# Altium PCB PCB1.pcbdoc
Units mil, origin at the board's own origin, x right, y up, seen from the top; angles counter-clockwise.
Board outline 2786 x 2316 mil, 2 copper layers (Top Layer, Bottom Layer), stack 62.2 mil thick; 3 components, 3 nets, 9 pads, 115 vias.
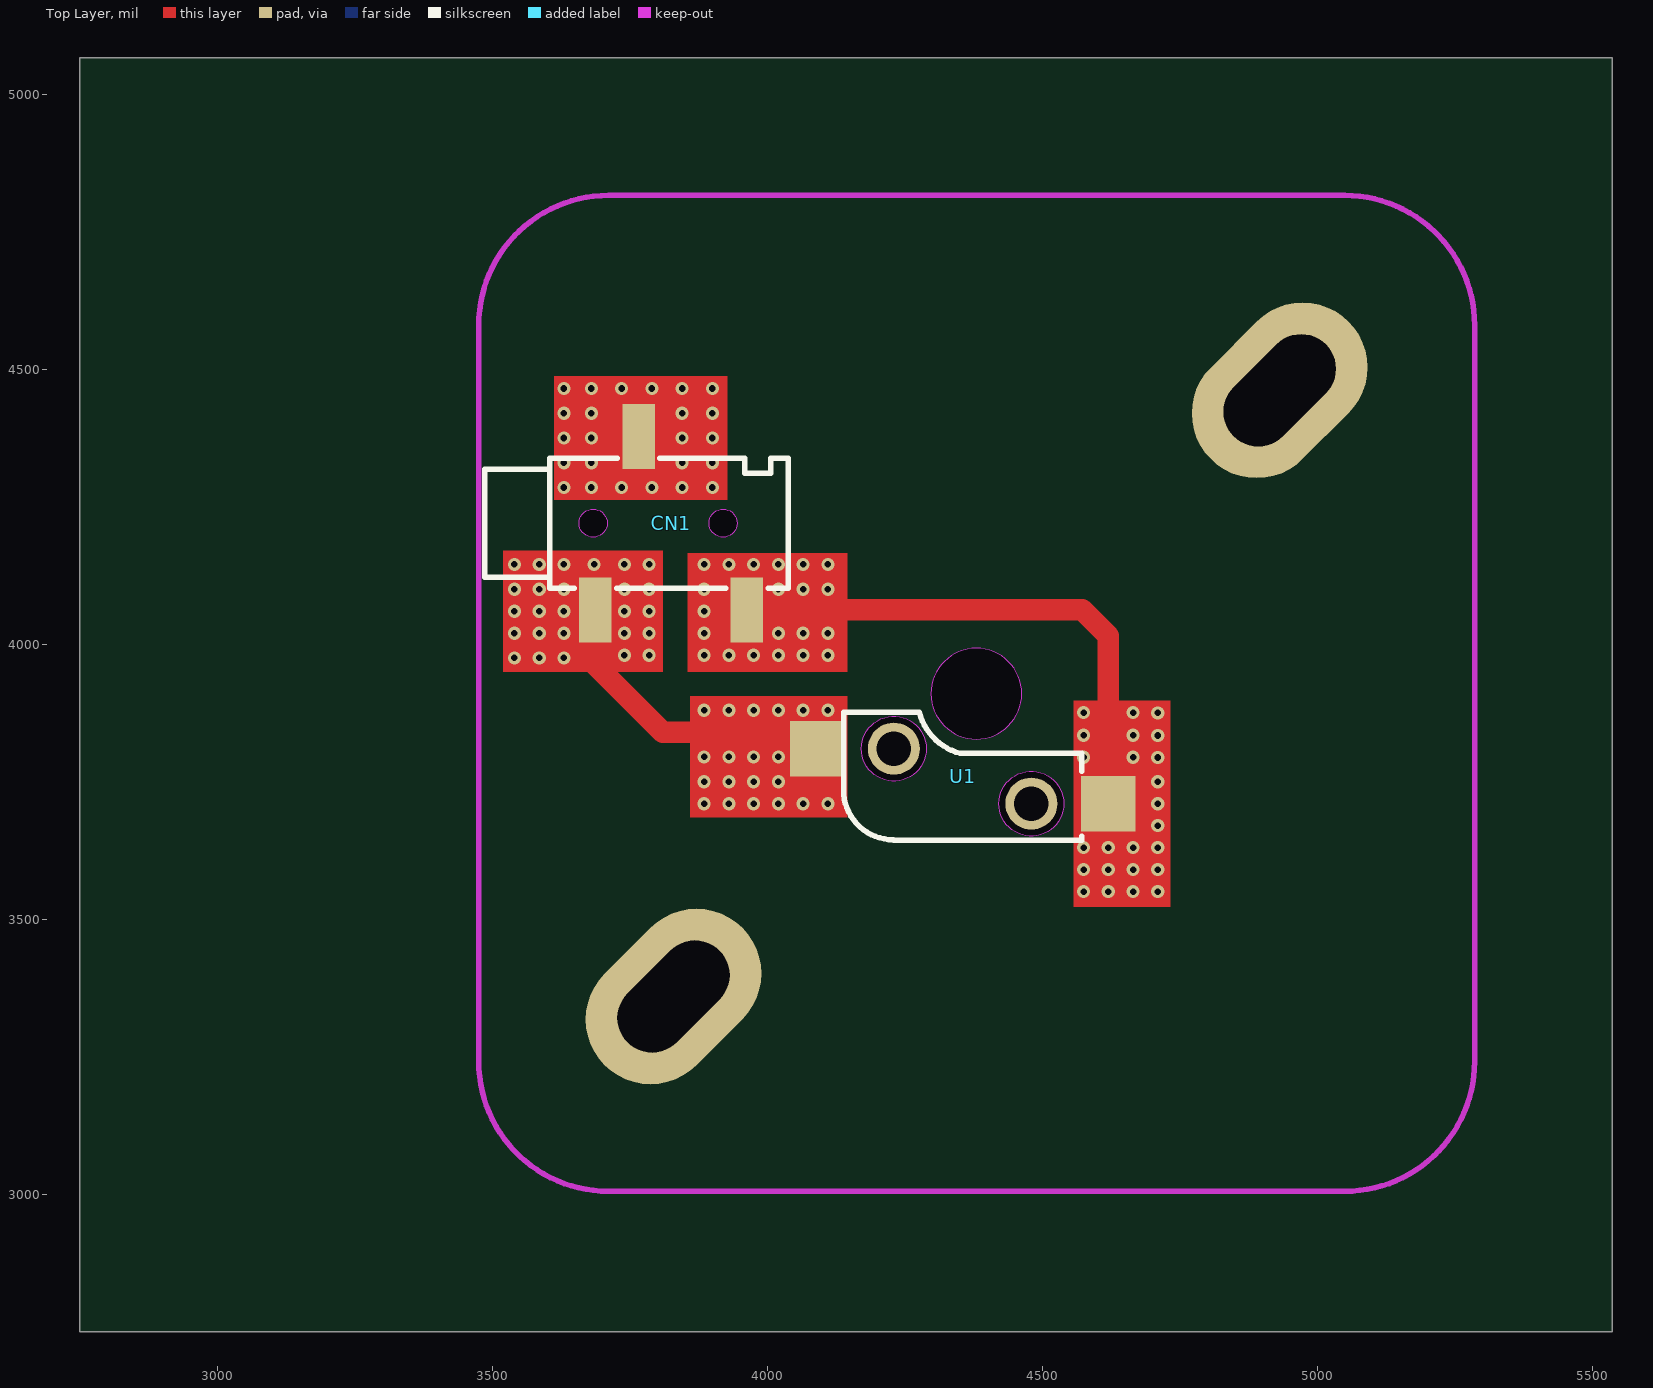
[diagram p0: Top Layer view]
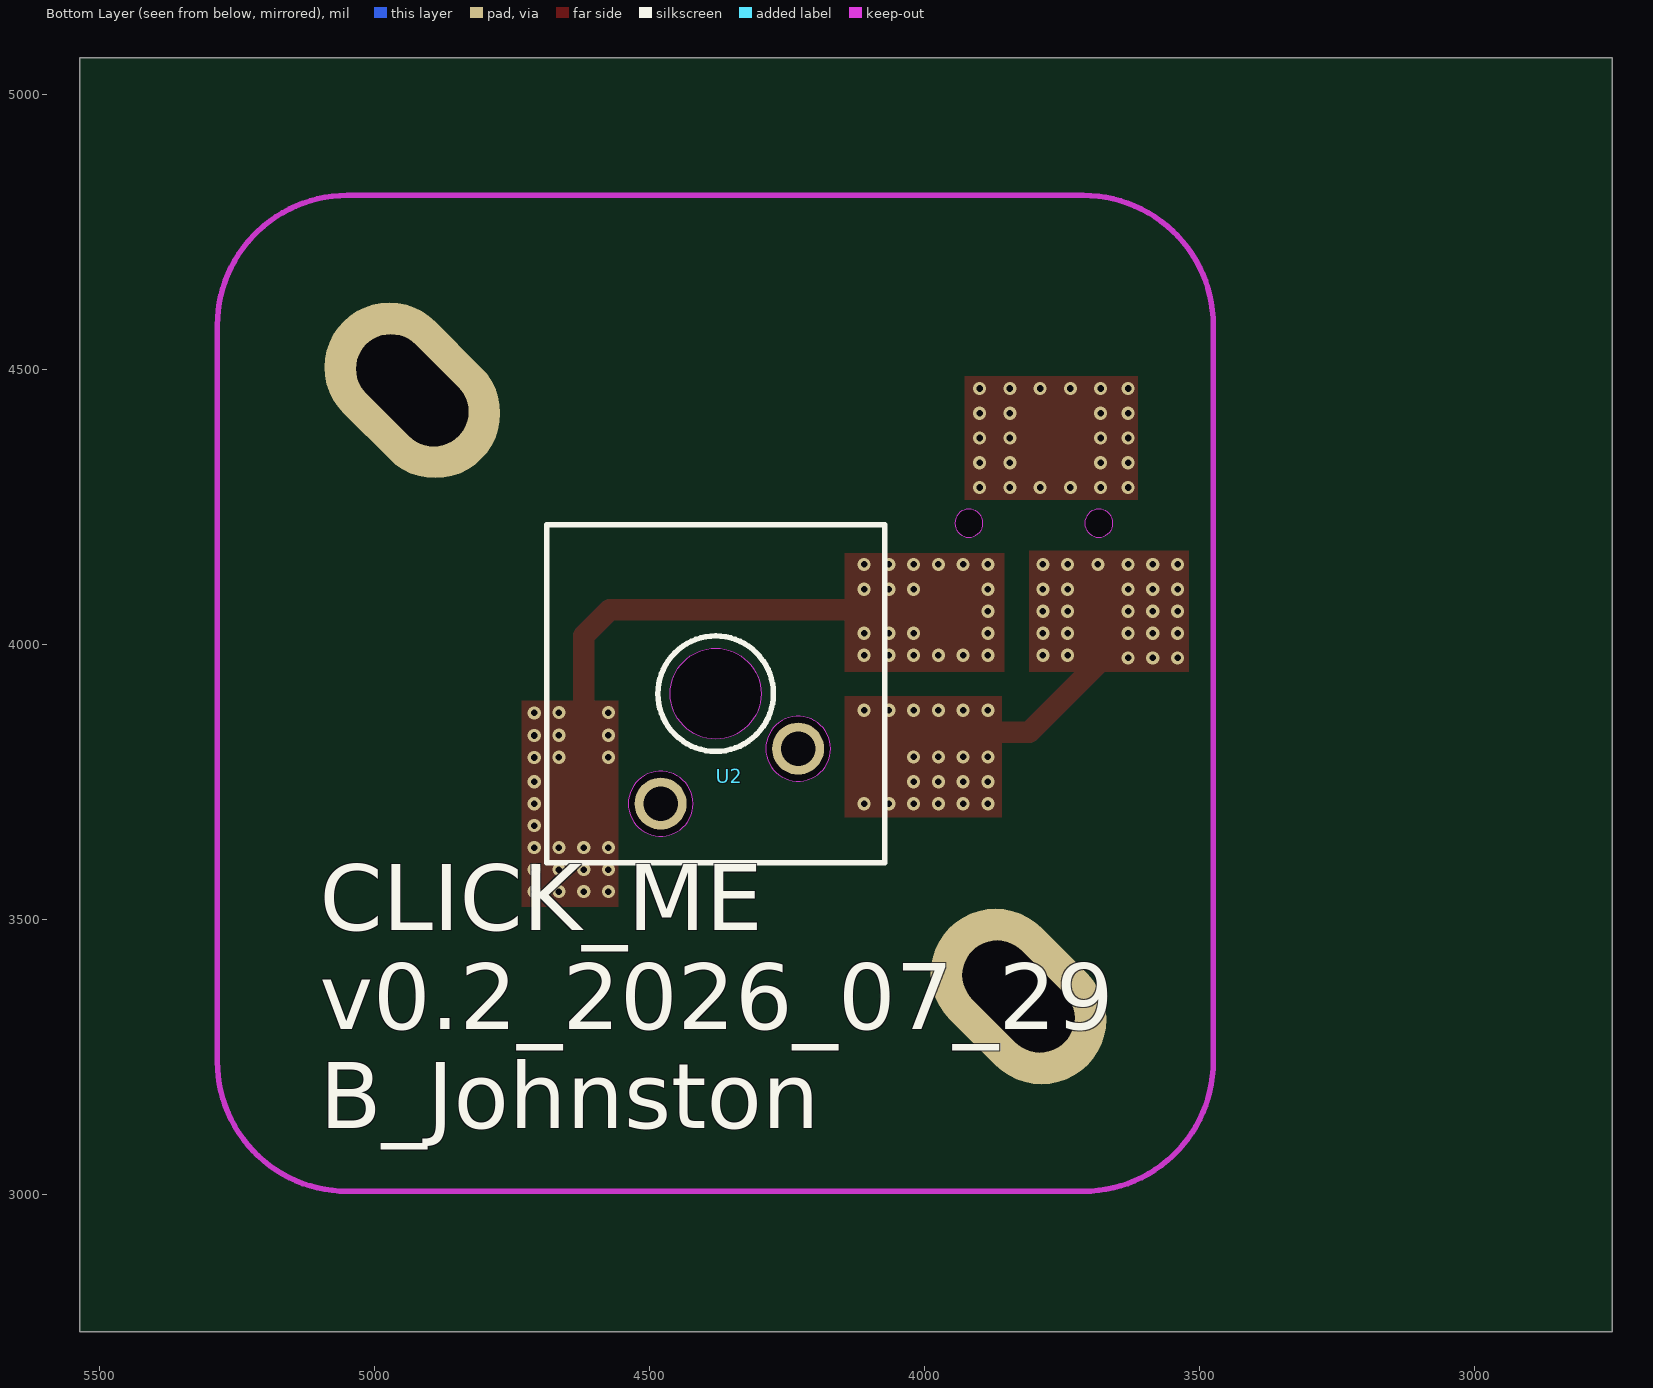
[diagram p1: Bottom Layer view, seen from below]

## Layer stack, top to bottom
Top Solder Mask Layer: solder mask 0.4, Dk 3.3
Top Layer: signal copper 1.4
Dielectric1: surface 59.4, FR4, Dk 4.5
Bottom Layer: signal copper 1.4
Bottom Solder Mask Layer: solder mask 0.4, Dk 3.3

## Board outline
5536,2750 2750,2750 2750,5066 5536,5066

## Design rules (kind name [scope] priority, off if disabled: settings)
BoardOutlineClearance copperThickness1oz [All] p0: genericclearance=10 ignorepadtopadclearanceinfootprint=FALSE except(0: Arc-SplitContinuation Track-SplitContinuation SMDPad-SplitContinuation THPad-SplitContinuation Via-SplitContinuation Fill-SplitContinuation Poly-SplitContinuation Region-SplitContinuation Text-SplitContinuation)
BoardOutlineClearance copperThickness2oz [All] p0: genericclearance=10 ignorepadtopadclearanceinfootprint=FALSE except(0: Arc-SplitContinuation Track-SplitContinuation SMDPad-SplitContinuation THPad-SplitContinuation Via-SplitContinuation Fill-SplitContinuation Poly-SplitContinuation Region-SplitContinuation Text-SplitContinuation)
BoardOutlineClearance otherClearance [All] p0: genericclearance=10 ignorepadtopadclearanceinfootprint=FALSE except(0: Arc-SplitContinuation Track-SplitContinuation SMDPad-SplitContinuation THPad-SplitContinuation Via-SplitContinuation Fill-SplitContinuation Poly-SplitContinuation Region-SplitContinuation Text-SplitContinuation)
Clearance copperThickness1oz [All] p1: gap=7 ignorepadtopadclearanceinfootprint=FALSE
Clearance copperThickness2oz [All] p1: gap=7 ignorepadtopadclearanceinfootprint=FALSE
Clearance otherClearance [All] p1: gap=7 ignorepadtopadclearanceinfootprint=FALSE
DiffPairsRouting differentialPair [All] p1: maxuncoupledlength=10 minlimit=6 maxlimit=Infinity mostfreqgap=6 toplayer_minwidth=5 toplayer_prefwidth=10 toplayer_maxwidth=100 bottomlayer_minwidth=5 bottomlayer_prefwidth=10 bottomlayer_maxwidth=100
PasteMaskExpansion pasteMaskExpansion [All] p1: expansion=0
PlaneConnect innerPlane [All] p1: planeconnectstyle=Relief reliefexpansion=20 reliefentries=4 reliefconductorwidth=10 reliefairgap=10
PolygonConnect copperRegion [All] p1: connectstyle=Relief reliefentries=4 reliefconductorwidth=10 polygonreliefangle="90 Angle" airgapwidth=10
RoutingVias viaSize [All] p1: viastyle="Through Hole" holewidth=12.0078 minholewidth=11.811 maxholewidth=248.0314 width=12.0078 minwidth=11.811 maxwidth=248.0314
SolderMaskExpansion solderMaskExpansion [IsVia] p1: useseparateexpansions=TRUE expansion=-1000 expansionbottom=-1000
SolderMaskExpansion solderMaskExpansion [All] p2: useseparateexpansions=TRUE expansion=2 expansionbottom=2
Width copperThickness1oz [All] p1: maxlimit=100 minlimit=5 preferedwidth=10
Width copperThickness2oz [All] p1: maxlimit=100 minlimit=8 preferedwidth=10

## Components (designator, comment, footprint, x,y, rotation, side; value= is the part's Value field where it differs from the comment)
CN1 "PJ-320B" AUDIO-SMD_PJ-320B 3825,4220 r90 top
U1 "CPG151101S11-16" SMD_KEYBOARD-SW 4355,3760 r0 top
U2 "CPG151101D13" KEY-TH_CPG151101D21X 4355,3760 r0 bottom

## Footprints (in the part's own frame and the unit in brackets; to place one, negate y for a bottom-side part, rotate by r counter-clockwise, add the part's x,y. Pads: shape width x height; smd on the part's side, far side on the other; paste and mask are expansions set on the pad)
AUDIO-SMD_PJ-320B [mil]
  rect 118.1x59.1 smd: 1(-157.5,137.8) 2(157.5,59.1) 3(-157.5,-137.8)
  Board Outline Layer lines w0.1: 0,167.3 -4.4,166.9 -8.8,165.8 -12.8,163.9 -16.4,161.3 -19.6,158.2 -22.2,154.5 -24,150.5 -25.2,146.2 -25.6,141.7 -25.2,137.3 -24,133 -22.2,128.9 -19.6,125.3 -16.4,122.1 -12.8,119.6 -8.8,117.7 -4.4,116.5 0,116.1 4.4,116.5 8.8,117.7 12.8,119.6 16.4,122.1 19.6,125.3 22.2,128.9 24,133 25.2,137.3 25.6,141.7 25.2,146.2 24,150.5 22.2,154.5 19.6,158.2 16.4,161.3 12.8,163.9 8.8,165.8 4.4,166.9 0,167.3 ; 0,-68.9 -4.4,-69.3 -8.8,-70.4 -12.8,-72.3 -16.4,-74.9 -19.6,-78 -22.2,-81.7 -24,-85.7 -25.2,-90 -25.6,-94.5 -25.2,-98.9 -24,-103.2 -22.2,-107.3 -19.6,-110.9 -16.4,-114.1 -12.8,-116.6 -8.8,-118.5 -4.4,-119.7 0,-120.1 4.4,-119.7 8.8,-118.5 12.8,-116.6 16.4,-114.1 19.6,-110.9 22.2,-107.3 24,-103.2 25.2,-98.9 25.6,-94.5 25.2,-90 24,-85.7 22.2,-81.7 19.6,-78 16.4,-74.9 12.8,-72.3 8.8,-70.4 4.4,-69.3 0,-68.9
  Board Outline Layer region: 25.6,141.7 25.2,137.3 24,133 22.2,128.9 19.6,125.3 16.4,122.1 12.8,119.6 8.8,117.7 4.4,116.5 0,116.1 -4.4,116.5 -8.8,117.7 -12.8,119.6 -16.4,122.1 -19.6,125.3 -22.2,128.9 -24,133 -25.2,137.3 -25.6,141.7 -25.2,146.2 -24,150.5 -22.2,154.5 -19.6,158.2 -16.4,161.3 -12.8,163.9 -8.8,165.8 -4.4,166.9 0,167.3 4.4,166.9 8.8,165.8 12.8,163.9 16.4,161.3 19.6,158.2 22.2,154.5 24,150.5 25.2,146.2
  Board Outline Layer region: 25.6,141.7 25.2,137.3 24,133 22.2,128.9 19.6,125.3 16.4,122.1 12.8,119.6 8.8,117.7 4.4,116.5 0,116.1 -4.4,116.5 -8.8,117.7 -12.8,119.6 -16.4,122.1 -19.6,125.3 -22.2,128.9 -24,133 -25.2,137.3 -25.6,141.7 -25.2,146.2 -24,150.5 -22.2,154.5 -19.6,158.2 -16.4,161.3 -12.8,163.9 -8.8,165.8 -4.4,166.9 0,167.3 4.4,166.9 8.8,165.8 12.8,163.9 16.4,161.3 19.6,158.2 22.2,154.5 24,150.5 25.2,146.2
  Board Outline Layer region: 25.6,-94.5 25.2,-98.9 24,-103.2 22.2,-107.3 19.6,-110.9 16.4,-114.1 12.8,-116.6 8.8,-118.5 4.4,-119.7 0,-120.1 -4.4,-119.7 -8.8,-118.5 -12.8,-116.6 -16.4,-114.1 -19.6,-110.9 -22.2,-107.3 -24,-103.2 -25.2,-98.9 -25.6,-94.5 -25.2,-90 -24,-85.7 -22.2,-81.7 -19.6,-78 -16.4,-74.9 -12.8,-72.3 -8.8,-70.4 -4.4,-69.3 0,-68.9 4.4,-69.3 8.8,-70.4 12.8,-72.3 16.4,-74.9 19.6,-78 22.2,-81.7 24,-85.7 25.2,-90
  Board Outline Layer region: 25.6,-94.5 25.2,-98.9 24,-103.2 22.2,-107.3 19.6,-110.9 16.4,-114.1 12.8,-116.6 8.8,-118.5 4.4,-119.7 0,-120.1 -4.4,-119.7 -8.8,-118.5 -12.8,-116.6 -16.4,-114.1 -19.6,-110.9 -22.2,-107.3 -24,-103.2 -25.2,-98.9 -25.6,-94.5 -25.2,-90 -24,-85.7 -22.2,-81.7 -19.6,-78 -16.4,-74.9 -12.8,-72.3 -8.8,-70.4 -4.4,-69.3 0,-68.9 4.4,-69.3 8.8,-70.4 12.8,-72.3 16.4,-74.9 19.6,-78 22.2,-81.7 24,-85.7 25.2,-90
  Multi-Layer board cut-out: 25.6,141.7 25.2,137.3 24,133 22.2,128.9 19.6,125.3 16.4,122.1 12.8,119.6 8.8,117.7 4.4,116.5 0,116.1 -4.4,116.5 -8.8,117.7 -12.8,119.6 -16.4,122.1 -19.6,125.3 -22.2,128.9 -24,133 -25.2,137.3 -25.6,141.7 -25.2,146.2 -24,150.5 -22.2,154.5 -19.6,158.2 -16.4,161.3 -12.8,163.9 -8.8,165.8 -4.4,166.9 0,167.3 4.4,166.9 8.8,165.8 12.8,163.9 16.4,161.3 19.6,158.2 22.2,154.5 24,150.5 25.2,146.2
  Multi-Layer board cut-out: 25.6,-94.5 25.2,-98.9 24,-103.2 22.2,-107.3 19.6,-110.9 16.4,-114.1 12.8,-116.6 8.8,-118.5 4.4,-119.7 0,-120.1 -4.4,-119.7 -8.8,-118.5 -12.8,-116.6 -16.4,-114.1 -19.6,-110.9 -22.2,-107.3 -24,-103.2 -25.2,-98.9 -25.6,-94.5 -25.2,-90 -24,-85.7 -22.2,-81.7 -19.6,-78 -16.4,-74.9 -12.8,-72.3 -8.8,-70.4 -4.4,-69.3 0,-68.9 4.4,-69.3 8.8,-70.4 12.8,-72.3 16.4,-74.9 19.6,-78 22.2,-81.7 24,-85.7 25.2,-90
  silkscreen extent -118,-213 118,339
KEY-TH_CPG151101D21X [mil]
  round 94.5 hole 63: 1(-125,-50) 2(125,50)
  Board Outline Layer lines w0.1: -57.7,-150 -57.3,-158.1 -56.1,-166.1 -54.1,-174 -51.4,-181.6 -47.9,-189 -43.7,-195.9 -38.9,-202.4 -33.5,-208.5 -27.4,-213.9 -20.9,-218.7 -14,-222.9 -6.6,-226.4 1,-229.1 8.9,-231.1 16.9,-232.3 25,-232.7 33.1,-232.3 41.1,-231.1 49,-229.1 56.6,-226.4 64,-222.9 70.9,-218.7 77.4,-213.9 83.5,-208.5 88.9,-202.4 93.7,-195.9 97.9,-189 101.4,-181.6 104.1,-174 106.1,-166.1 107.3,-158.1 107.7,-150 107.3,-141.9 106.1,-133.9 104.1,-126 101.4,-118.4 97.9,-111 93.7,-104.1 88.9,-97.6 83.5,-91.5 77.4,-86.1 70.9,-81.3 64,-77.1 56.6,-73.6 49,-70.9 41.1,-68.9 33.1,-67.7 25,-67.3 16.9,-67.7 8.9,-68.9 1,-70.9 -6.6,-73.6 -14,-77.1 -20.9,-81.3 -27.4,-86.1 -33.5,-91.5 -38.9,-97.6 -43.7,-104.1 -47.9,-111 -51.4,-118.4 -54.1,-126 -56.1,-133.9 -57.3,-141.9 -57.7,-150
  Board Outline Layer region: 107.7,-150 107.3,-158.1 106.1,-166.1 104.1,-174 101.4,-181.6 97.9,-189 93.7,-195.9 88.9,-202.4 83.5,-208.5 77.4,-213.9 70.9,-218.7 64,-222.9 56.6,-226.4 49,-229.1 41.1,-231.1 33.1,-232.3 25,-232.7 16.9,-232.3 8.9,-231.1 1,-229.1 -6.6,-226.4 -14,-222.9 -20.9,-218.7 -27.4,-213.9 -33.5,-208.5 -38.9,-202.4 -43.7,-195.9 -47.9,-189 -51.4,-181.6 -54.1,-174 -56.1,-166.1 -57.3,-158.1 -57.7,-150 -57.3,-141.9 -56.1,-133.9 -54.1,-126 -51.4,-118.4 -47.9,-111 -43.7,-104.1 -38.9,-97.6 -33.5,-91.5 -27.4,-86.1 -20.9,-81.3 -14,-77.1 -6.6,-73.6 1,-70.9 8.9,-68.9 16.9,-67.7 25,-67.3 33.1,-67.7 41.1,-68.9 49,-70.9 56.6,-73.6 64,-77.1 70.9,-81.3 77.4,-86.1 83.5,-91.5 88.9,-97.6 93.7,-104.1 97.9,-111 101.4,-118.4 104.1,-126 106.1,-133.9 107.3,-141.9
  Board Outline Layer region: 107.7,-150 107.3,-158.1 106.1,-166.1 104.1,-174 101.4,-181.6 97.9,-189 93.7,-195.9 88.9,-202.4 83.5,-208.5 77.4,-213.9 70.9,-218.7 64,-222.9 56.6,-226.4 49,-229.1 41.1,-231.1 33.1,-232.3 25,-232.7 16.9,-232.3 8.9,-231.1 1,-229.1 -6.6,-226.4 -14,-222.9 -20.9,-218.7 -27.4,-213.9 -33.5,-208.5 -38.9,-202.4 -43.7,-195.9 -47.9,-189 -51.4,-181.6 -54.1,-174 -56.1,-166.1 -57.3,-158.1 -57.7,-150 -57.3,-141.9 -56.1,-133.9 -54.1,-126 -51.4,-118.4 -47.9,-111 -43.7,-104.1 -38.9,-97.6 -33.5,-91.5 -27.4,-86.1 -20.9,-81.3 -14,-77.1 -6.6,-73.6 1,-70.9 8.9,-68.9 16.9,-67.7 25,-67.3 33.1,-67.7 41.1,-68.9 49,-70.9 56.6,-73.6 64,-77.1 70.9,-81.3 77.4,-86.1 83.5,-91.5 88.9,-97.6 93.7,-104.1 97.9,-111 101.4,-118.4 104.1,-126 106.1,-133.9 107.3,-141.9
  Multi-Layer board cut-out: 107.7,-150 107.3,-158.1 106.1,-166.1 104.1,-174 101.4,-181.6 97.9,-189 93.7,-195.9 88.9,-202.4 83.5,-208.5 77.4,-213.9 70.9,-218.7 64,-222.9 56.6,-226.4 49,-229.1 41.1,-231.1 33.1,-232.3 25,-232.7 16.9,-232.3 8.9,-231.1 1,-229.1 -6.6,-226.4 -14,-222.9 -20.9,-218.7 -27.4,-213.9 -33.5,-208.5 -38.9,-202.4 -43.7,-195.9 -47.9,-189 -51.4,-181.6 -54.1,-174 -56.1,-166.1 -57.3,-158.1 -57.7,-150 -57.3,-141.9 -56.1,-133.9 -54.1,-126 -51.4,-118.4 -47.9,-111 -43.7,-104.1 -38.9,-97.6 -33.5,-91.5 -27.4,-86.1 -20.9,-81.3 -14,-77.1 -6.6,-73.6 1,-70.9 8.9,-68.9 16.9,-67.7 25,-67.3 33.1,-67.7 41.1,-68.9 49,-70.9 56.6,-73.6 64,-77.1 70.9,-81.3 77.4,-86.1 83.5,-91.5 88.9,-97.6 93.7,-104.1 97.9,-111 101.4,-118.4 104.1,-126 106.1,-133.9 107.3,-141.9
  silkscreen extent -282,-457 332,157
SMD_KEYBOARD-SW [mil]
  rect 98.4x100.4 smd paste+0 mask+2: 1(-264.8,50) 2(264.8,-50)
  Board Outline Layer lines w0.1: -184.1,50 -183.7,43.1 -182.5,36.4 -180.5,29.8 -177.8,23.5 -174.3,17.5 -170.2,12 -165.5,7 -160.3,2.6 -154.5,-1.1 -148.4,-4.2 -141.9,-6.6 -135.3,-8.2 -128.4,-9 -121.6,-9 -114.7,-8.2 -108.1,-6.6 -101.6,-4.2 -95.5,-1.1 -89.7,2.6 -84.5,7 -79.8,12 -75.7,17.5 -72.2,23.5 -69.5,29.8 -67.5,36.4 -66.3,43.1 -65.9,50 -66.3,56.9 -67.5,63.6 -69.5,70.2 -72.2,76.5 -75.7,82.5 -79.8,88 -84.5,93 -89.7,97.4 -95.5,101.1 -101.6,104.2 -108.1,106.6 -114.7,108.2 -121.6,109 -128.4,109 -135.3,108.2 -141.9,106.6 -148.4,104.2 -154.5,101.1 -160.3,97.4 -165.5,93 -170.2,88 -174.3,82.5 -177.8,76.5 -180.5,70.2 -182.5,63.6 -183.7,56.9 -184.1,50 ; 65.9,-50 66.3,-56.9 67.5,-63.6 69.5,-70.2 72.2,-76.5 75.7,-82.5 79.8,-88 84.5,-93 89.7,-97.4 95.5,-101.1 101.6,-104.2 108.1,-106.6 114.7,-108.2 121.6,-109 128.4,-109 135.3,-108.2 141.9,-106.6 148.4,-104.2 154.5,-101.1 160.3,-97.4 165.5,-93 170.2,-88 174.3,-82.5 177.8,-76.5 180.5,-70.2 182.5,-63.6 183.7,-56.9 184.1,-50 183.7,-43.1 182.5,-36.4 180.5,-29.8 177.8,-23.5 174.3,-17.5 170.2,-12 165.5,-7 160.3,-2.6 154.5,1.1 148.4,4.2 141.9,6.6 135.3,8.2 128.4,9 121.6,9 114.7,8.2 108.1,6.6 101.6,4.2 95.5,1.1 89.7,-2.6 84.5,-7 79.8,-12 75.7,-17.5 72.2,-23.5 69.5,-29.8 67.5,-36.4 66.3,-43.1 65.9,-50
  Board Outline Layer region: -65.9,50 -66.3,43.1 -67.5,36.4 -69.5,29.8 -72.2,23.5 -75.7,17.5 -79.8,12 -84.5,7 -89.7,2.6 -95.5,-1.1 -101.6,-4.2 -108.1,-6.6 -114.7,-8.2 -121.6,-9 -128.4,-9 -135.3,-8.2 -141.9,-6.6 -148.4,-4.2 -154.5,-1.1 -160.3,2.6 -165.5,7 -170.2,12 -174.3,17.5 -177.8,23.5 -180.5,29.8 -182.5,36.4 -183.7,43.1 -184.1,50 -183.7,56.9 -182.5,63.6 -180.5,70.2 -177.8,76.5 -174.3,82.5 -170.2,88 -165.5,93 -160.3,97.4 -154.5,101.1 -148.4,104.2 -141.9,106.6 -135.3,108.2 -128.4,109 -121.6,109 -114.7,108.2 -108.1,106.6 -101.6,104.2 -95.5,101.1 -89.7,97.4 -84.5,93 -79.8,88 -75.7,82.5 -72.2,76.5 -69.5,70.2 -67.5,63.6 -66.3,56.9
  Board Outline Layer region: -65.9,50 -66.3,43.1 -67.5,36.4 -69.5,29.8 -72.2,23.5 -75.7,17.5 -79.8,12 -84.5,7 -89.7,2.6 -95.5,-1.1 -101.6,-4.2 -108.1,-6.6 -114.7,-8.2 -121.6,-9 -128.4,-9 -135.3,-8.2 -141.9,-6.6 -148.4,-4.2 -154.5,-1.1 -160.3,2.6 -165.5,7 -170.2,12 -174.3,17.5 -177.8,23.5 -180.5,29.8 -182.5,36.4 -183.7,43.1 -184.1,50 -183.7,56.9 -182.5,63.6 -180.5,70.2 -177.8,76.5 -174.3,82.5 -170.2,88 -165.5,93 -160.3,97.4 -154.5,101.1 -148.4,104.2 -141.9,106.6 -135.3,108.2 -128.4,109 -121.6,109 -114.7,108.2 -108.1,106.6 -101.6,104.2 -95.5,101.1 -89.7,97.4 -84.5,93 -79.8,88 -75.7,82.5 -72.2,76.5 -69.5,70.2 -67.5,63.6 -66.3,56.9
  Board Outline Layer region: 184.1,-50 183.7,-56.9 182.5,-63.6 180.5,-70.2 177.8,-76.5 174.3,-82.5 170.2,-88 165.5,-93 160.3,-97.4 154.5,-101.1 148.4,-104.2 141.9,-106.6 135.3,-108.2 128.4,-109 121.6,-109 114.7,-108.2 108.1,-106.6 101.6,-104.2 95.5,-101.1 89.7,-97.4 84.5,-93 79.8,-88 75.7,-82.5 72.2,-76.5 69.5,-70.2 67.5,-63.6 66.3,-56.9 65.9,-50 66.3,-43.1 67.5,-36.4 69.5,-29.8 72.2,-23.5 75.7,-17.5 79.8,-12 84.5,-7 89.7,-2.6 95.5,1.1 101.6,4.2 108.1,6.6 114.7,8.2 121.6,9 128.4,9 135.3,8.2 141.9,6.6 148.4,4.2 154.5,1.1 160.3,-2.6 165.5,-7 170.2,-12 174.3,-17.5 177.8,-23.5 180.5,-29.8 182.5,-36.4 183.7,-43.1
  Board Outline Layer region: 184.1,-50 183.7,-56.9 182.5,-63.6 180.5,-70.2 177.8,-76.5 174.3,-82.5 170.2,-88 165.5,-93 160.3,-97.4 154.5,-101.1 148.4,-104.2 141.9,-106.6 135.3,-108.2 128.4,-109 121.6,-109 114.7,-108.2 108.1,-106.6 101.6,-104.2 95.5,-101.1 89.7,-97.4 84.5,-93 79.8,-88 75.7,-82.5 72.2,-76.5 69.5,-70.2 67.5,-63.6 66.3,-56.9 65.9,-50 66.3,-43.1 67.5,-36.4 69.5,-29.8 72.2,-23.5 75.7,-17.5 79.8,-12 84.5,-7 89.7,-2.6 95.5,1.1 101.6,4.2 108.1,6.6 114.7,8.2 121.6,9 128.4,9 135.3,8.2 141.9,6.6 148.4,4.2 154.5,1.1 160.3,-2.6 165.5,-7 170.2,-12 174.3,-17.5 177.8,-23.5 180.5,-29.8 182.5,-36.4 183.7,-43.1
  Multi-Layer board cut-out: -65.9,50 -66.3,43.1 -67.5,36.4 -69.5,29.8 -72.2,23.5 -75.7,17.5 -79.8,12 -84.5,7 -89.7,2.6 -95.5,-1.1 -101.6,-4.2 -108.1,-6.6 -114.7,-8.2 -121.6,-9 -128.4,-9 -135.3,-8.2 -141.9,-6.6 -148.4,-4.2 -154.5,-1.1 -160.3,2.6 -165.5,7 -170.2,12 -174.3,17.5 -177.8,23.5 -180.5,29.8 -182.5,36.4 -183.7,43.1 -184.1,50 -183.7,56.9 -182.5,63.6 -180.5,70.2 -177.8,76.5 -174.3,82.5 -170.2,88 -165.5,93 -160.3,97.4 -154.5,101.1 -148.4,104.2 -141.9,106.6 -135.3,108.2 -128.4,109 -121.6,109 -114.7,108.2 -108.1,106.6 -101.6,104.2 -95.5,101.1 -89.7,97.4 -84.5,93 -79.8,88 -75.7,82.5 -72.2,76.5 -69.5,70.2 -67.5,63.6 -66.3,56.9
  Multi-Layer board cut-out: 184.1,-50 183.7,-56.9 182.5,-63.6 180.5,-70.2 177.8,-76.5 174.3,-82.5 170.2,-88 165.5,-93 160.3,-97.4 154.5,-101.1 148.4,-104.2 141.9,-106.6 135.3,-108.2 128.4,-109 121.6,-109 114.7,-108.2 108.1,-106.6 101.6,-104.2 95.5,-101.1 89.7,-97.4 84.5,-93 79.8,-88 75.7,-82.5 72.2,-76.5 69.5,-70.2 67.5,-63.6 66.3,-56.9 65.9,-50 66.3,-43.1 67.5,-36.4 69.5,-29.8 72.2,-23.5 75.7,-17.5 79.8,-12 84.5,-7 89.7,-2.6 95.5,1.1 101.6,4.2 108.1,6.6 114.7,8.2 121.6,9 128.4,9 135.3,8.2 141.9,6.6 148.4,4.2 154.5,1.1 160.3,-2.6 165.5,-7 170.2,-12 174.3,-17.5 177.8,-23.5 180.5,-29.8 182.5,-36.4 183.7,-43.1
  silkscreen extent -216,-116 216,116

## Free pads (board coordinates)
  oval 354.3x236.2 hole 126 slot 236.2 at 45 deg rot 45: 1(3829.3,3359.3) 1(4931.7,4461.7)

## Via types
v1: diameter 24, hole 12, Top Layer to Bottom Layer, 115 vias

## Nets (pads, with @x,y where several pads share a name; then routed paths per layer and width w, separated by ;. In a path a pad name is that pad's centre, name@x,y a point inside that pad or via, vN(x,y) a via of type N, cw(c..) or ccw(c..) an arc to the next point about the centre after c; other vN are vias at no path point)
$1N1: CN1.1 U1.1 | length 566
  Top Layer w39.4: CN1.1 3687.2,3962.8 3810,3840 4060.2,3840 U1.1
  other v1: 3885,3710 3930,3710 3975,3710 4020,3710 4065,3710 4110,3710 3885,3750 3930,3750 3975,3750 4020,3750 3885,3795 3930,3795 3975,3795 4020,3795 3885,3880 3930,3880 3975,3880 4020,3880 4065,3880 4110,3880 3540,3975 3585,3975 3630,3975 3740,3980 3785,3980 3540,4020 3585,4020 3630,4020 3740,4020 3785,4020 3540,4060 3585,4060 3630,4060 3740,4060 3785,4060 3540,4100 3585,4100 3630,4100 3740,4100 3785,4100 3540,4145 3585,4145 3630,4145 3685,4145 3740,4145 3785,4145
$1N2: CN1.3 U1.2 | length 981.8
  Top Layer w39.4: CN1.3 4572.5,4062.5 4619.8,4015.2 U1.2
  other v1: 4575,3550 4620,3550 4665,3550 4710,3550 4575,3590 4620,3590 4665,3590 4710,3590 4575,3630 4620,3630 4665,3630 4710,3630 4710,3670 4710,3710 4710,3750 4575,3794.5 4665,3794.5 4710,3794 4575,3834.5 4665,3834.5 4710,3834 4710,3875 4575,3875.5 4665,3875.5 3885,3980 3930,3980 3975,3980 4020,3980 4065,3980 4110,3980 3885,4020 4020,4020 4065,4020 4110,4020 3885,4060 3885,4100 4020,4100 4065,4100 4110,4100 3885,4145 3930,4145 3975,4145 4020,4145 4065,4145 4110,4145
UNCON: CN1.2
  other v1: 3630,4285 3680,4285 3735,4285 3790,4285 3845,4285 3900,4285 3630,4330 3680,4330 3845,4330 3900,4330 3630,4375 3680,4375 3845,4375 3900,4375 3630,4420 3680,4420 3845,4420 3900,4420 3630,4465 3680,4465 3735,4465 3790,4465 3845,4465 3900,4465
pads on no net: U2.1 U2.2

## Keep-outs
Board Outline Layer:
  lines w10: 3475,3241.2 3475.4,3227.5 3476.6,3213.8 3478.6,3200.2 3481.4,3186.7 3484.9,3173.5 3489.2,3160.4 3494.3,3147.7 3500.1,3135.2 3506.6,3123.1 3513.9,3111.4 3521.7,3100.2 3530.3,3089.4 3539.4,3079.1 3549.1,3069.4 3559.4,3060.3 3570.2,3051.7 3581.4,3043.9 3593.1,3036.6 3605.2,3030.1 3617.7,3024.3 3630.4,3019.2 3643.5,3014.9 3656.7,3011.4 3670.2,3008.6 3683.8,3006.6 3697.5,3005.4 3711.2,3005 5049.8,3005 5063.5,3005.4 5077.2,3006.6 5090.8,3008.6 5104.3,3011.4 5117.6,3014.9 5130.6,3019.2 5143.4,3024.3 5155.8,3030.1 5167.9,3036.6 5179.6,3043.9 5190.9,3051.7 5201.6,3060.3 5211.9,3069.4 5221.6,3079.1 5230.8,3089.4 5239.3,3100.2 5247.2,3111.4 5254.4,3123.1 5260.9,3135.2 5266.7,3147.7 5271.8,3160.4 5276.1,3173.5 5279.7,3186.7 5282.4,3200.2 5284.4,3213.8 5285.6,3227.5 5286,3241.2 5286,4579.8 5285.6,4593.5 5284.4,4607.2 5282.4,4620.8 5279.7,4634.3 5276.1,4647.6 5271.8,4660.6 5266.7,4673.4 5260.9,4685.8 5254.4,4697.9 5247.2,4709.6 5239.3,4720.9 5230.8,4731.6 5221.6,4741.9 5211.9,4751.6 5201.6,4760.8 5190.9,4769.3 5179.6,4777.2 5167.9,4784.4 5155.8,4790.9 5143.4,4796.7 5130.6,4801.8 5117.6,4806.1 5104.3,4809.7 5090.8,4812.4 5077.2,4814.4 5063.5,4815.6 5049.8,4816 3711.2,4816 3697.5,4815.6 3683.8,4814.4 3670.2,4812.4 3656.7,4809.7 3643.5,4806.1 3630.4,4801.8 3617.7,4796.7 3605.2,4790.9 3593.1,4784.4 3581.4,4777.2 3570.2,4769.3 3559.4,4760.8 3549.1,4751.6 3539.4,4741.9 3530.3,4731.6 3521.7,4720.9 3513.9,4709.6 3506.6,4697.9 3500.1,4685.8 3494.3,4673.4 3489.2,4660.6 3484.9,4647.6 3481.4,4634.3 3478.6,4620.8 3476.6,4607.2 3475.4,4593.5 3475,4579.8 3475,3241.2

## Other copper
Top Layer:
  region net $1N1: 3520,4170 3520,3950 3810,3950 3810,4170
  region net $1N2: 4732.5,3897.5 4557.5,3897.5 4557.5,3522.5 4732.5,3522.5
  region net UNCON: 3612.5,4487.5 3612.5,4262.5 3927.5,4262.5 3927.5,4487.5
  region net $1N2: 3855,4165 3855,3950 4145,3950 4145,4165
  region net $1N1: 3860,3905 3860,3685 4145,3685 4145,3905

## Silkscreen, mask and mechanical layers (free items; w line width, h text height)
Bottom Silkscreen Layer:
  lines w10: 4072.9,3602.9 4072.9,4217.1 4687.1,4217.1 4687.1,3602.9 4072.9,3602.9 ; 4275,3910 4275.4,3900.8 4276.6,3891.8 4278.6,3882.8 4281.3,3874.1 4284.8,3865.6 4289.1,3857.5 4294,3849.8 4299.6,3842.5 4305.8,3835.8 4312.5,3829.6 4319.8,3824 4327.5,3819.1 4335.6,3814.8 4344.1,3811.3 4352.8,3808.6 4361.8,3806.6 4370.8,3805.4 4380,3805 4389.2,3805.4 4398.2,3806.6 4407.2,3808.6 4415.9,3811.3 4424.4,3814.8 4432.5,3819.1 4440.2,3824 4447.5,3829.6 4454.2,3835.8 4460.4,3842.5 4466,3849.8 4470.9,3857.5 4475.2,3865.6 4478.7,3874.1 4481.4,3882.8 4483.4,3891.8 4484.6,3900.8 4485,3910 4484.6,3919.2 4483.4,3928.2 4481.4,3937.2 4478.7,3945.9 4475.2,3954.4 4470.9,3962.5 4466,3970.2 4460.4,3977.5 4454.2,3984.2 4447.5,3990.4 4440.2,3996 4432.5,4000.9 4424.4,4005.2 4415.9,4008.7 4407.2,4011.4 4398.2,4013.4 4389.2,4014.6 4380,4015 4370.8,4014.6 4361.8,4013.4 4352.8,4011.4 4344.1,4008.7 4335.6,4005.2 4327.5,4000.9 4319.8,3996 4312.5,3990.4 4305.8,3984.2 4299.6,3977.5 4294,3970.2 4289.1,3962.5 4284.8,3954.4 4281.3,3945.9 4278.6,3937.2 4276.6,3928.2 4275.4,3919.2 4275,3910
  text "CLICK_ME / v0.2_2026_07_29 / B_Johnston" at 5100,3120 h120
